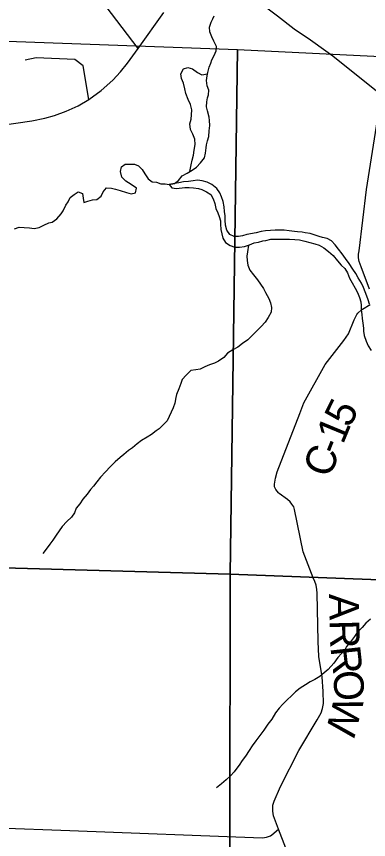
# Model space of a CAD drawing. Extents: x 0 to 34, y 0 to 22.
# Drawn here: x 4.875 to 5.549, y 14.969 to 16.545 of the extents above; entities that cross this region are included whole.
import ezdxf

# ---------------------------------------------------------------- set-up
doc = ezdxf.new("R2010")
doc.units = 0
doc.layers.add('Default', color=7, linetype='Continuous')

msp = doc.modelspace()

# ---------------------------------------------------------------- linework, layer by layer
at = {"layer": 'Default'}
for p, q in [((5.1077, 16.4842), (5.157, 16.5526)), ((4.7599, 14.9946), (4.977, 14.9865))]:
    msp.add_line(p, q, dxfattribs=at)
for points in [[(5.5861, 16.3845), (5.5724, 16.3953), (5.5193, 16.4381), (5.4802, 16.4691), (5.4669, 16.4789), (5.4374, 16.4998), (5.4065, 16.5213), (5.3742, 16.5456), (5.3315, 16.5782), (5.283, 16.6114), (5.2424, 16.6404), (5.2378, 16.6435)], [(5.1077, 16.4842), (5.0362, 16.5783), (5.0356, 16.5795), (5.0353, 16.5809), (5.0353, 16.5831), (5.0355, 16.5848), (5.0361, 16.5861), (5.0366, 16.5867), (5.0372, 16.5874), (5.0384, 16.5883), (5.0942, 16.6228)], [(5.0568, 16.2167), (5.0644, 16.2146), (5.0736, 16.212), (5.0854, 16.208), (5.0942, 16.2055), (5.1025, 16.2079), (5.1043, 16.2163), (5.0943, 16.2237), (5.0843, 16.2297), (5.0766, 16.2379), (5.0738, 16.2485), (5.0759, 16.2573), (5.0831, 16.2627), (5.091, 16.2628), (5.1009, 16.2622), (5.1086, 16.2596), (5.1155, 16.2525), (5.1206, 16.2438), (5.1268, 16.2344), (5.1344, 16.2289), (5.1428, 16.2278), (5.1508, 16.2249), (5.1592, 16.2247), (5.1672, 16.2233), (5.177, 16.2253), (5.1849, 16.2315), (5.192, 16.2399), (5.2014, 16.245), (5.2112, 16.2512), (5.2191, 16.257), (5.2273, 16.2651), (5.2344, 16.2747), (5.2366, 16.2835), (5.2379, 16.2941), (5.2386, 16.2998), (5.2404, 16.3074), (5.2429, 16.3158), (5.2439, 16.3265), (5.2449, 16.3364), (5.244, 16.3462), (5.2435, 16.3527), (5.2407, 16.3644), (5.2387, 16.3723), (5.2389, 16.3818), (5.2407, 16.3894), (5.2425, 16.3955), (5.2428, 16.4039), (5.2396, 16.4122), (5.2383, 16.4224), (5.2397, 16.4316), (5.2412, 16.4381), (5.2437, 16.448), (5.247, 16.456), (5.2488, 16.4621), (5.2532, 16.4705), (5.2569, 16.4797), (5.2579, 16.488), (5.2524, 16.4982), (5.2489, 16.5065), (5.2446, 16.5159), (5.2445, 16.5247), (5.2473, 16.5346), (5.2503, 16.5407), (5.2529, 16.5464)], [(4.6523, 16.309), (4.8427, 16.3364), (4.9041, 16.3453), (4.9289, 16.3504), (4.9478, 16.3556), (4.9699, 16.364), (4.9932, 16.3745), (5.0136, 16.3866), (5.037, 16.4037), (5.0592, 16.4236), (5.0737, 16.4394), (5.0873, 16.4557), (5.1077, 16.4842)], [(5.0136, 16.3866), (5.0024, 16.4506), (4.9864, 16.4629), (4.9127, 16.4658), (4.8916, 16.4618)], [(5.2066, 16.2483), (5.2092, 16.2614), (5.2113, 16.2702), (5.2135, 16.2797), (5.2152, 16.2896), (5.2166, 16.3003), (5.2164, 16.3105), (5.2125, 16.3199), (5.2078, 16.3286), (5.2069, 16.3396), (5.2094, 16.3484), (5.2101, 16.3571), (5.2103, 16.3666), (5.2079, 16.3765), (5.2032, 16.3866), (5.1992, 16.3976), (5.1968, 16.407), (5.1944, 16.4176), (5.1904, 16.4263), (5.1892, 16.4354), (5.1947, 16.445), (5.2027, 16.4474), (5.2118, 16.4448), (5.221, 16.4378), (5.2298, 16.4333), (5.2406, 16.4356)], [(5.5506, 16.0234), (5.5345, 16.0659), (5.5306, 16.0761), (5.5295, 16.0833), (5.5295, 16.0905), (5.5303, 16.0963), (5.5447, 16.2139), (5.579, 16.4321)], [(4.8711, 16.1385), (4.8798, 16.1417), (4.8896, 16.1415), (4.8999, 16.1409), (4.9087, 16.1395), (4.9181, 16.1415), (4.9272, 16.1458), (4.937, 16.1501), (4.9434, 16.1517), (4.9521, 16.1579), (4.9606, 16.1675), (4.964, 16.1733), (4.9695, 16.184), (4.9736, 16.1905), (4.9777, 16.1985), (4.9856, 16.2047), (4.9931, 16.2094), (5.0011, 16.2061), (5.0024, 16.1974), (5.004, 16.1894), (5.0116, 16.1914), (5.0203, 16.1942), (5.0286, 16.1951), (5.0369, 16.2013), (5.0409, 16.2093), (5.0469, 16.2174), (5.0568, 16.2167)], [(5.5503, 15.9944), (5.5479, 16.0028), (5.5455, 16.0096), (5.5423, 16.0183), (5.5388, 16.0262), (5.5353, 16.0349), (5.529, 16.0446), (5.5244, 16.0533), (5.5185, 16.0616), (5.5112, 16.0725), (5.5042, 16.0819), (5.4984, 16.0909), (5.491, 16.0995), (5.4848, 16.1078), (5.4775, 16.116), (5.4691, 16.1201), (5.4603, 16.1223), (5.4542, 16.1241), (5.4367, 16.1299), (5.4271, 16.1313), (5.4214, 16.1323), (5.4123, 16.133), (5.4066, 16.1336), (5.3967, 16.1346), (5.3872, 16.136), (5.3781, 16.1363), (5.3701, 16.1362), (5.361, 16.1356), (5.3511, 16.1351), (5.3428, 16.1335), (5.3333, 16.1311), (5.3159, 16.1278), (5.3072, 16.1254), (5.2997, 16.1238), (5.2913, 16.124), (5.2833, 16.1277), (5.2771, 16.136), (5.2746, 16.1458), (5.2741, 16.1553), (5.274, 16.1636), (5.2731, 16.172), (5.2722, 16.1811), (5.2706, 16.1913), (5.2674, 16.2), (5.2643, 16.2079), (5.2584, 16.2162), (5.2488, 16.2237), (5.2397, 16.2281), (5.2305, 16.2306), (5.2214, 16.2316), (5.213, 16.2307), (5.2039, 16.2291), (5.1948, 16.2286), (5.1857, 16.2269), (5.177, 16.2253), (5.1672, 16.2233)], [(5.1672, 16.2233), (5.1722, 16.2169), (5.181, 16.2162), (5.1969, 16.218), (5.2052, 16.2181), (5.2136, 16.2171), (5.2231, 16.2157), (5.2296, 16.2143), (5.2388, 16.2098), (5.2468, 16.2043), (5.2511, 16.196), (5.2547, 16.1873), (5.2563, 16.1778), (5.2603, 16.1695), (5.263, 16.162), (5.265, 16.154), (5.2655, 16.1476), (5.266, 16.1377), (5.2681, 16.129), (5.2697, 16.1211), (5.2748, 16.1124), (5.2836, 16.1068), (5.2927, 16.1039), (5.3015, 16.1037), (5.3109, 16.1046), (5.3208, 16.1081), (5.3298, 16.1117), (5.3378, 16.1133), (5.3461, 16.1157), (5.3518, 16.1165), (5.3616, 16.1186), (5.3711, 16.1191), (5.378, 16.1188), (5.3973, 16.1191), (5.4072, 16.1185), (5.4167, 16.1175), (5.4266, 16.1153), (5.4361, 16.1128), (5.4457, 16.1099), (5.4541, 16.1074), (5.4629, 16.1025), (5.4717, 16.0955), (5.4809, 16.0876), (5.4891, 16.0775), (5.4964, 16.0689), (5.503, 16.0625), (5.508, 16.0542), (5.5123, 16.044), (5.5174, 16.035), (5.5229, 16.0252), (5.5272, 16.0169), (5.5311, 16.0075), (5.5335, 15.9988), (5.5344, 15.9919), (5.5345, 15.9836), (5.5354, 15.9749), (5.5362, 15.9673), (5.5375, 15.9578), (5.5388, 15.9487), (5.5389, 15.943), (5.5401, 15.9343), (5.5441, 15.9234), (5.5476, 15.9147), (5.5538, 15.906)], [(5.3191, 16.1075), (5.3172, 16.0944), (5.3158, 16.0864), (5.3163, 16.0781), (5.3179, 16.0694), (5.3215, 16.0595), (5.3284, 16.0505), (5.3358, 16.0411), (5.3416, 16.0325), (5.3474, 16.0242), (5.3513, 16.0167), (5.3576, 16.005), (5.3607, 15.9971), (5.3628, 15.988), (5.3621, 15.9789), (5.3566, 15.9689), (5.3506, 15.9601), (5.3432, 15.952), (5.3346, 15.9435), (5.326, 15.9343), (5.3173, 15.9262), (5.3076, 15.9192), (5.2982, 15.9123), (5.2888, 15.9068), (5.2786, 15.9006), (5.2715, 15.8925), (5.2617, 15.8855), (5.2538, 15.8816), (5.244, 15.8781), (5.2353, 15.8742), (5.2262, 15.8702), (5.2179, 15.869), (5.2088, 15.8673), (5.1995, 15.8588), (5.192, 15.85), (5.1891, 15.8427), (5.1854, 15.8324), (5.1814, 15.8218), (5.18, 15.8157), (5.1778, 15.805), (5.1749, 15.7962), (5.1712, 15.7874), (5.1635, 15.7714), (5.1568, 15.7645), (5.1482, 15.756), (5.1421, 15.7521), (5.1331, 15.7448), (5.1252, 15.7397), (5.1143, 15.7335), (5.1057, 15.7273), (5.0967, 15.7196), (5.0891, 15.7145), (5.0805, 15.7068), (5.073, 15.7006), (5.064, 15.6925), (5.0543, 15.6829), (5.0453, 15.6733), (5.0356, 15.6633), (5.0289, 15.654), (5.0222, 15.646), (5.0166, 15.6394), (5.0102, 15.6306), (5.0016, 15.621), (4.9964, 15.6122), (4.9894, 15.6037), (4.9857, 15.595), (4.9801, 15.5865), (4.9715, 15.5784), (4.9621, 15.5688), (4.9569, 15.5607), (4.9506, 15.5519), (4.9443, 15.5427), (4.9387, 15.5347), (4.9316, 15.5251), (4.9253, 15.517)], [(5.4615, 14.7681), (5.3761, 14.9891), (5.367, 15.0149), (5.3654, 15.0236), (5.3652, 15.0311), (5.3657, 15.0354), (5.368, 15.043), (5.3801, 15.0709), (5.4152, 15.1402), (5.4503, 15.1984), (5.4578, 15.2117), (5.4605, 15.2206), (5.4622, 15.2297), (5.4617, 15.253), (5.4601, 15.281), (5.4532, 15.3198), (5.4521, 15.3487), (5.45, 15.4411), (5.4498, 15.448), (5.4483, 15.4567), (5.4459, 15.4633), (5.4428, 15.4707), (5.4236, 15.52), (5.4071, 15.6012), (5.4054, 15.6062), (5.402, 15.6118), (5.3989, 15.6157), (5.3935, 15.6205), (5.3774, 15.6317), (5.3762, 15.633), (5.3711, 15.6395), (5.3687, 15.6449), (5.3685, 15.6499), (5.3704, 15.6616), (5.3739, 15.6732), (5.4172, 15.7851), (5.4246, 15.8053), (5.4657, 15.8788), (5.501, 15.9251), (5.51, 15.9378), (5.5211, 15.9642), (5.5263, 15.9745), (5.5282, 15.9771), (5.5353, 15.9837), (5.5373, 15.9852), (5.5516, 15.9938)], [(5.5526, 15.3915), (5.5432, 15.3838), (5.5361, 15.3753), (5.5256, 15.3638), (5.5219, 15.358), (5.5141, 15.3481), (5.5062, 15.3392), (5.5033, 15.3327), (5.4969, 15.3254), (5.4898, 15.3177), (5.4824, 15.3073), (5.4716, 15.295), (5.4637, 15.2885), (5.4554, 15.2819), (5.446, 15.2761), (5.437, 15.2714), (5.4279, 15.2659), (5.4178, 15.2593), (5.4091, 15.2524), (5.4002, 15.2439), (5.3934, 15.2373), (5.3848, 15.2285), (5.3777, 15.2208), (5.3706, 15.212), (5.3632, 15.1997), (5.3557, 15.1901), (5.3483, 15.179), (5.3405, 15.1686), (5.3326, 15.1586), (5.326, 15.149), (5.3204, 15.1399), (5.3133, 15.1291), (5.3066, 15.1207), (5.301, 15.1119), (5.2966, 15.1061), (5.2914, 15.0992), (5.2843, 15.0915), (5.276, 15.0838), (5.2674, 15.0761), (5.2576, 15.0687)], [(4.977, 14.9865), (5.345, 14.9728), (5.3494, 14.9732), (5.3534, 14.974), (5.3573, 14.9752), (5.361, 14.9768), (5.3636, 14.9787), (5.3761, 14.9891)]]:
    msp.add_lwpolyline(points, dxfattribs=at)
for points in [[(4.2574, 16.5198), (5.2975, 16.482), (5.284, 15.4777), (4.2566, 15.5062)], [(5.2975, 16.482), (6.2896, 16.4334), (6.2943, 15.9991), (6.2933, 15.4392), (5.284, 15.4777)], [(4.2566, 15.5062), (5.284, 15.4777), (5.2822, 14.472), (4.2629, 14.5006)], [(5.284, 15.4777), (6.2933, 15.4392), (6.2908, 15.0024), (6.2858, 14.4391), (5.2822, 14.472)]]:
    msp.add_lwpolyline(points, close=True, dxfattribs=at)

# ---------------------------------------------------------------- texts
for s, rotation, p in [('5', 63.7538, (5.5125, 15.756)), ('1', 67.5531, (5.4996, 15.7245)), ('-', 68.5595, (5.4911, 15.7031)), ('C', 68.8414, (5.4743, 15.6596)), ('A', 271.184, (5.4729, 15.4397)), ('R', 271.428, (5.474, 15.3895)), ('R', 276.2971, (5.4755, 15.3376)), ('O', 273.9081, (5.4806, 15.2918)), ('W', 255.435, (5.4844, 15.2467))]:
    msp.add_text(s, height=0.0568, rotation=rotation, dxfattribs=at).set_placement(p)

doc.saveas('drawing.dxf')
